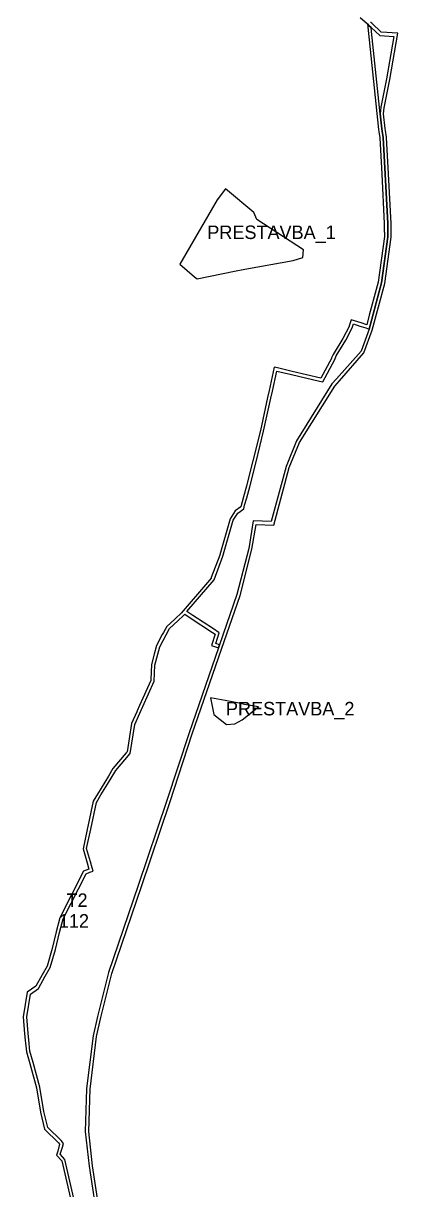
# Model space of a CAD drawing. Extents: x -477001 to -465642, y -1158278 to -1150672.
# Drawn here: x -475565 to -475233, y -1153120 to -1152085 of the extents above; entities that cross this region are included whole.
import ezdxf

# ---------------------------------------------------------------- set-up
doc = ezdxf.new("R2010")
doc.units = 0
for name, color, linetype in [('prestavba_n', 7, 'Continuous'), ('VPS_id', 7, 'Continuous'), ('VPS_n', 7, 'Continuous'), ('vyvlastneni_n', 7, 'Continuous')]:
    doc.layers.add(name, color=color, linetype=linetype)

msp = doc.modelspace()

# ---------------------------------------------------------------- linework, layer by layer
at = {"layer": 'prestavba_n'}
for p, q in [((-475385.7, -1152231.9), (-475392.9, -1152241.7)), ((-475360.4, -1152252.7), (-475385.7, -1152231.9)), ((-475392.9, -1152241.7), (-475426.2, -1152298.7)), ((-475357.7, -1152259.1), (-475360.4, -1152252.7)), ((-475316.3, -1152286.1), (-475357.7, -1152259.1)), ((-475316.8, -1152292.8), (-475316.3, -1152286.1)), ((-475368.3, -1152303.3), (-475325.4, -1152295.5)), ((-475325.4, -1152295.5), (-475316.8, -1152292.8)), ((-475426.2, -1152298.7), (-475413.1, -1152309.9)), ((-475413.1, -1152309.9), (-475410.8, -1152311.9)), ((-475385.9, -1152686.5), (-475398.9, -1152684.2)), ((-475373.6, -1152688.9), (-475385.9, -1152686.5)), ((-475384.8, -1152707.8), (-475377.4, -1152707.1))]:
    msp.add_line(p, q, dxfattribs=at)
for points in [[(-475410.8, -1152311.9), (-475377.7, -1152305.1), (-475368.3, -1152303.3)], [(-475398.9, -1152684.2), (-475396, -1152699), (-475384.8, -1152707.8)], [(-475377.4, -1152707.1), (-475370.7, -1152703.6), (-475356.4, -1152692.2), (-475368.8, -1152689.9), (-475373.6, -1152688.9)]]:
    msp.add_lwpolyline(points, dxfattribs=at)
at = {"layer": 'VPS_n'}
for p, q in [((-475265.9, -1152079.5), (-475259.5, -1152085.3)), ((-475259.5, -1152085.3), (-475257.8, -1152086.9)), ((-475257.8, -1152086.9), (-475259.5, -1152085.3)), ((-475259.5, -1152085.3), (-475249.7, -1152179)), ((-475257.8, -1152086.9), (-475256.2, -1152088.4)), ((-475256.2, -1152088.4), (-475257.8, -1152086.9)), ((-475255.8, -1152092.1), (-475256.2, -1152088.4)), ((-475248.1, -1152165.1), (-475255.8, -1152092.1)), ((-475243.7, -1152178.2), (-475245.1, -1152165.1)), ((-475249.7, -1152179), (-475249.4, -1152180.9)), ((-475249.4, -1152180.9), (-475248.4, -1152186.6)), ((-475246.7, -1152178.6), (-475246.7, -1152178.6)), ((-475246.7, -1152178.6), (-475246.7, -1152178.6)), ((-475238.4, -1152269.4), (-475238.5, -1152268.5)), ((-475273.9, -1152348.1), (-475275.7, -1152353.6)), ((-475271.1, -1152349), (-475273.9, -1152348.1)), ((-475265.1, -1152350.9), (-475271.1, -1152349)), ((-475257.9, -1152344.2), (-475260.1, -1152352.5)), ((-475273, -1152355.2), (-475272, -1152351.9)), ((-475272, -1152351.9), (-475266.3, -1152353.7)), ((-475266.3, -1152353.7), (-475265.2, -1152354)), ((-475265.2, -1152354), (-475260.9, -1152355.4)), ((-475260.1, -1152352.5), (-475265.1, -1152350.9)), ((-475288.6, -1152383.3), (-475287.3, -1152380.2)), ((-475339.4, -1152390.9), (-475342.4, -1152390.2)), ((-475326.3, -1152394), (-475339.4, -1152390.9)), ((-475291.5, -1152382.5), (-475300.8, -1152400)), ((-475299.2, -1152403.4), (-475288.6, -1152383.3)), ((-475340.1, -1152393.8), (-475327, -1152396.9)), ((-475327, -1152396.9), (-475302.2, -1152402.7)), ((-475300.8, -1152400), (-475326.3, -1152394)), ((-475302.2, -1152402.7), (-475299.2, -1152403.4)), ((-475351.7, -1152447.1), (-475345.4, -1152417.8)), ((-475358.5, -1152474.3), (-475351.7, -1152447.1)), ((-475364, -1152496.7), (-475358.5, -1152474.3)), ((-475364.8, -1152487.4), (-475366.9, -1152495.9)), ((-475366.9, -1152495.9), (-475369.6, -1152505.5)), ((-475366.7, -1152506.3), (-475364, -1152496.7)), ((-475369.4, -1152516.1), (-475368.6, -1152513)), ((-475368.6, -1152513), (-475366.7, -1152506.3)), ((-475378.8, -1152526.2), (-475374.8, -1152520)), ((-475374.8, -1152520), (-475369.4, -1152516.1)), ((-475387.9, -1152558.2), (-475378.8, -1152526.2)), ((-475395.8, -1152579.3), (-475387.9, -1152558.2)), ((-475419.9, -1152607.5), (-475395.8, -1152579.3)), ((-475414.6, -1152611), (-475419.9, -1152607.5)), ((-475430.7, -1152614.1), (-475437.9, -1152620.7)), ((-475435.5, -1152622.5), (-475428, -1152615.7)), ((-475421.8, -1152609.8), (-475416.9, -1152613)), ((-475416.9, -1152613), (-475397.3, -1152625.9)), ((-475396.3, -1152622.9), (-475414.6, -1152611)), ((-475444.1, -1152638.7), (-475435.5, -1152622.5)), ((-475440.8, -1152626), (-475441.8, -1152627.9)), ((-475437.9, -1152620.7), (-475440.8, -1152626)), ((-475448.5, -1152655.1), (-475444.1, -1152638.7)), ((-475449, -1152669.3), (-475448.5, -1152655.1)), ((-475452, -1152668.7), (-475462, -1152691)), ((-475459, -1152691.7), (-475449, -1152669.3)), ((-475451.9, -1152667.8), (-475452, -1152668.7)), ((-475462, -1152691), (-475464.1, -1152695.6)), ((-475464.5, -1152696.5), (-475469.1, -1152706.9)), ((-475466.3, -1152707.8), (-475461.7, -1152697.7)), ((-475464.1, -1152695.6), (-475464.5, -1152696.5)), ((-475461.7, -1152697.7), (-475459, -1152691.7)), ((-475470.3, -1152733.5), (-475466.3, -1152707.8)), ((-475473.1, -1152732.2), (-475473.8, -1152733)), ((-475489.7, -1152753.7), (-475499.3, -1152769.6)), ((-475496.3, -1152770.3), (-475490.4, -1152760.7)), ((-475507, -1152836.2), (-475511.7, -1152838)), ((-475508.5, -1152830.8), (-475507, -1152836.2)), ((-475504.2, -1152835.2), (-475505.7, -1152829.7)), ((-475503.3, -1152838), (-475504.2, -1152835.2)), ((-475530, -1152880.6), (-475509.5, -1152840.4)), ((-475509.5, -1152840.4), (-475506.1, -1152839.1)), ((-475506.1, -1152839.1), (-475503.3, -1152838)), ((-475533, -1152892.6), (-475530, -1152880.6)), ((-475536.8, -1152907.6), (-475533, -1152892.6)), ((-475541.5, -1152923.7), (-475536.8, -1152907.6)), ((-475545.8, -1152931.5), (-475541.5, -1152923.7)), ((-475533, -1153080.7), (-475534.7, -1153087)), ((-475532.4, -1153089.7), (-475530.6, -1153083.5)), ((-475530.6, -1153083.5), (-475529.6, -1153080)), ((-475534.7, -1153087), (-475535.7, -1153090.5)), ((-475535.7, -1153090.5), (-475531.1, -1153095.6)), ((-475528.3, -1153094.2), (-475532.4, -1153089.7))]:
    msp.add_line(p, q, dxfattribs=at)
for points in [[(-475245.1, -1152165.1), (-475244.5, -1152159.7), (-475239.6, -1152134.5), (-475232.6, -1152093.5), (-475247.3, -1152092.5), (-475255.7, -1152084.7), (-475256.5, -1152084.1), (-475256.7, -1152083.9)], [(-475256.2, -1152088.4), (-475248.6, -1152095.4), (-475236.1, -1152096.3), (-475242.5, -1152134), (-475247.5, -1152159.3), (-475248.1, -1152165.1)], [(-475248.1, -1152165.1), (-475246.7, -1152178.6), (-475246.7, -1152178.6)], [(-475246.7, -1152178.6), (-475246.7, -1152178.6), (-475248.1, -1152165.1)], [(-475246.7, -1152178.6), (-475246.4, -1152180.5), (-475245.4, -1152186.3), (-475245.4, -1152186.3)], [(-475245.4, -1152186.3), (-475245.4, -1152186.3), (-475246.4, -1152180.5), (-475246.7, -1152178.6)], [(-475242.4, -1152186.2), (-475242.5, -1152185.9), (-475243.4, -1152180), (-475243.7, -1152178.2)], [(-475260.9, -1152355.4), (-475258, -1152356.4), (-475247, -1152315.2), (-475241.3, -1152274.3), (-475241.3, -1152270.5), (-475241.5, -1152269.4), (-475241.5, -1152262.6), (-475243.7, -1152218.8), (-475245.4, -1152186.3)], [(-475245.4, -1152186.3), (-475243.7, -1152218.8), (-475241.5, -1152262.6), (-475241.5, -1152269.4), (-475241.3, -1152270.5), (-475241.3, -1152274.3), (-475247, -1152315.2), (-475258, -1152356.4)], [(-475248.4, -1152186.6), (-475246.7, -1152218.9), (-475244.5, -1152262.7)], [(-475238.5, -1152268.5), (-475238.5, -1152262.5), (-475240.7, -1152218.6), (-475242.4, -1152186.2)], [(-475244.5, -1152262.7), (-475244.5, -1152269.6), (-475244.3, -1152270.7), (-475244.3, -1152274.1)], [(-475244.3, -1152274.1), (-475249.9, -1152314.6), (-475257.9, -1152344.2)], [(-475255.2, -1152357.3), (-475244, -1152315.8), (-475238.3, -1152274.6), (-475238.3, -1152270.3), (-475238.4, -1152269.4)], [(-475275.7, -1152353.6), (-475275.8, -1152354), (-475281.4, -1152364.9), (-475290, -1152378.9), (-475290, -1152378.9)], [(-475287.3, -1152380.2), (-475278.8, -1152366.4), (-475273, -1152355.2)], [(-475258, -1152356.4), (-475265.2, -1152375.9), (-475287, -1152400.7)], [(-475284.4, -1152402.3), (-475262.6, -1152377.4), (-475255.2, -1152357.3)], [(-475290, -1152378.9), (-475291.3, -1152382.1), (-475291.5, -1152382.5)], [(-475342.4, -1152390.2), (-475346.9, -1152410.9), (-475348.3, -1152417.1), (-475348.3, -1152417.2)], [(-475345.4, -1152417.8), (-475343.9, -1152411.5), (-475340.1, -1152393.8)], [(-475287, -1152400.7), (-475291, -1152405.2), (-475322.6, -1152455.8), (-475331.7, -1152478.4), (-475345, -1152527.5)], [(-475342.7, -1152530.6), (-475328.9, -1152479.4), (-475319.9, -1152457.2), (-475288.5, -1152407), (-475284.4, -1152402.3)], [(-475348.3, -1152417.2), (-475354.6, -1152446.5), (-475354.6, -1152446.5)], [(-475354.6, -1152446.5), (-475361.4, -1152473.6), (-475364.8, -1152487.4)], [(-475372, -1152514.3), (-475377, -1152517.9), (-475381.5, -1152525), (-475390.7, -1152557.1)], [(-475369.6, -1152505.5), (-475369.6, -1152505.5), (-475372, -1152514.3)], [(-475345, -1152527.5), (-475361, -1152526.9), (-475365, -1152551.5), (-475375.5, -1152592.4)], [(-475372.6, -1152593.3), (-475362.1, -1152552.1), (-475358.5, -1152530), (-475342.7, -1152530.6)], [(-475390.7, -1152557.1), (-475390.7, -1152557.2), (-475398.3, -1152577.3)], [(-475398.3, -1152577.3), (-475398.5, -1152577.8), (-475401.7, -1152581.5)], [(-475401.7, -1152581.5), (-475425.1, -1152608.9), (-475430.1, -1152613.5), (-475430.7, -1152614.1)], [(-475375.5, -1152592.4), (-475390.9, -1152636.9), (-475391.9, -1152639.8), (-475391.9, -1152639.8), (-475417.9, -1152715.2), (-475438, -1152776.2), (-475463.1, -1152850.7), (-475489.6, -1152928.1), (-475499.3, -1152967.3), (-475503.1, -1152984.4), (-475509, -1153031.1)], [(-475506, -1153031.7), (-475500.2, -1152984.9), (-475496.4, -1152968), (-475486.7, -1152928.9), (-475460.3, -1152851.7), (-475435.1, -1152777.1), (-475415.1, -1152716.2), (-475389.1, -1152640.8), (-475372.6, -1152593.3)], [(-475428, -1152615.7), (-475422.9, -1152611), (-475421.8, -1152609.8)], [(-475441.8, -1152627.9), (-475446.9, -1152637.6), (-475449, -1152645.3)], [(-475397.3, -1152625.9), (-475394.7, -1152627.6), (-475398, -1152637.6), (-475391.9, -1152639.8), (-475390.9, -1152636.9), (-475394.2, -1152635.7), (-475391.2, -1152626.3), (-475396.3, -1152622.9)], [(-475449, -1152645.3), (-475451.5, -1152654.6), (-475451.9, -1152667.8)], [(-475469.1, -1152706.9), (-475469.2, -1152707), (-475473.1, -1152732.2)], [(-475473.8, -1152733), (-475485.6, -1152746.9), (-475489.7, -1152753.7)], [(-475490.4, -1152760.7), (-475483.1, -1152748.6), (-475470.3, -1152733.5)], [(-475499.3, -1152769.6), (-475503.2, -1152775.9), (-475508.6, -1152801.1)], [(-475505.4, -1152800.9), (-475500.3, -1152777), (-475496.3, -1152770.3)], [(-475508.6, -1152801.1), (-475512.2, -1152818.2), (-475508.5, -1152830.8)], [(-475505.7, -1152829.7), (-475509.1, -1152818.1), (-475505.4, -1152800.9)], [(-475511.7, -1152838), (-475532.9, -1152879.6), (-475536, -1152891.9), (-475539.7, -1152906.9), (-475544.2, -1152922.5), (-475548.4, -1152930.1), (-475554.2, -1152940.4), (-475561.8, -1152945.6), (-475565.3, -1152967.5), (-475564.1, -1152982.6), (-475563.5, -1152988.4), (-475562.4, -1152998.7), (-475559.5, -1153009.1)], [(-475529.6, -1153080), (-475531.8, -1153077.5), (-475543.6, -1153066), (-475547.1, -1153051.6), (-475550.5, -1153030), (-475556.6, -1153008.2), (-475559.4, -1152998.2), (-475560.5, -1152988.1), (-475561.1, -1152982.4), (-475562.3, -1152967.6), (-475559, -1152947.3), (-475551.9, -1152942.4), (-475545.8, -1152931.5)], [(-475559.5, -1153009.1), (-475553.5, -1153030.7), (-475550.1, -1153052.2), (-475546.4, -1153067.5), (-475534, -1153079.5), (-475533, -1153080.7)], [(-475509, -1153031.1), (-475509, -1153031.6), (-475510.2, -1153069.5), (-475506.9, -1153100.2), (-475498.7, -1153153)], [(-475495.8, -1153152.4), (-475503.9, -1153099.8), (-475507.2, -1153069.4), (-475506, -1153031.8), (-475506, -1153031.7)], [(-475511.1, -1153235.2), (-475512.5, -1153231.1), (-475517.9, -1153214.8), (-475521.2, -1153204.9), (-475525.3, -1153189.2), (-475525.6, -1153187.1), (-475516.8, -1153144.3), (-475528.3, -1153094.2)], [(-475531.1, -1153095.6), (-475519.9, -1153144.4), (-475528.7, -1153187), (-475528.3, -1153189.8), (-475524.1, -1153205.8), (-475520.8, -1153215.7), (-475515.3, -1153232), (-475513.9, -1153236.2), (-475508.5, -1153250.6), (-475505.8, -1153256.7), (-475500.9, -1153265.2), (-475496.9, -1153271.7), (-475486.2, -1153282.2), (-475476.4, -1153289.8), (-475468.6, -1153294.7), (-475459, -1153315.2), (-475453.4, -1153327.2), (-475445.8, -1153344.1), (-475428.9, -1153403.2)]]:
    msp.add_lwpolyline(points, dxfattribs=at)
at = {"layer": 'vyvlastneni_n'}
for p, q in [((-475265.9, -1152079.5), (-475259.5, -1152085.3)), ((-475259.5, -1152085.3), (-475257.8, -1152086.9)), ((-475257.8, -1152086.9), (-475259.5, -1152085.3)), ((-475259.5, -1152085.3), (-475249.7, -1152179)), ((-475257.8, -1152086.9), (-475256.2, -1152088.4)), ((-475256.2, -1152088.4), (-475257.8, -1152086.9)), ((-475255.8, -1152092.1), (-475256.2, -1152088.4)), ((-475248.1, -1152165.1), (-475255.8, -1152092.1)), ((-475243.7, -1152178.2), (-475245.1, -1152165.1)), ((-475249.7, -1152179), (-475249.4, -1152180.9)), ((-475249.4, -1152180.9), (-475248.4, -1152186.6)), ((-475246.7, -1152178.6), (-475246.7, -1152178.6)), ((-475246.7, -1152178.6), (-475246.7, -1152178.6)), ((-475238.4, -1152269.4), (-475238.5, -1152268.5)), ((-475273.9, -1152348.1), (-475275.7, -1152353.6)), ((-475271.1, -1152349), (-475273.9, -1152348.1)), ((-475265.1, -1152350.9), (-475271.1, -1152349)), ((-475257.9, -1152344.2), (-475260.1, -1152352.5)), ((-475273, -1152355.2), (-475272, -1152351.9)), ((-475272, -1152351.9), (-475266.3, -1152353.7)), ((-475266.3, -1152353.7), (-475265.2, -1152354)), ((-475265.2, -1152354), (-475260.9, -1152355.4)), ((-475260.1, -1152352.5), (-475265.1, -1152350.9)), ((-475288.6, -1152383.3), (-475287.3, -1152380.2)), ((-475339.4, -1152390.9), (-475342.4, -1152390.2)), ((-475326.3, -1152394), (-475339.4, -1152390.9)), ((-475291.5, -1152382.5), (-475300.8, -1152400)), ((-475299.2, -1152403.4), (-475288.6, -1152383.3)), ((-475340.1, -1152393.8), (-475327, -1152396.9)), ((-475327, -1152396.9), (-475302.2, -1152402.7)), ((-475300.8, -1152400), (-475326.3, -1152394)), ((-475302.2, -1152402.7), (-475299.2, -1152403.4)), ((-475351.7, -1152447.1), (-475345.4, -1152417.8)), ((-475358.5, -1152474.3), (-475351.7, -1152447.1)), ((-475364, -1152496.7), (-475358.5, -1152474.3)), ((-475364.8, -1152487.4), (-475366.9, -1152495.9)), ((-475366.9, -1152495.9), (-475369.6, -1152505.5)), ((-475366.7, -1152506.3), (-475364, -1152496.7)), ((-475369.4, -1152516.1), (-475368.6, -1152513)), ((-475368.6, -1152513), (-475366.7, -1152506.3)), ((-475378.8, -1152526.2), (-475374.8, -1152520)), ((-475374.8, -1152520), (-475369.4, -1152516.1)), ((-475387.9, -1152558.2), (-475378.8, -1152526.2)), ((-475395.8, -1152579.3), (-475387.9, -1152558.2)), ((-475419.9, -1152607.5), (-475395.8, -1152579.3)), ((-475414.6, -1152611), (-475419.9, -1152607.5)), ((-475430.7, -1152614.1), (-475437.9, -1152620.7)), ((-475435.5, -1152622.5), (-475428, -1152615.7)), ((-475421.8, -1152609.8), (-475416.9, -1152613)), ((-475416.9, -1152613), (-475397.3, -1152625.9)), ((-475396.3, -1152622.9), (-475414.6, -1152611)), ((-475444.1, -1152638.7), (-475435.5, -1152622.5)), ((-475440.8, -1152626), (-475441.8, -1152627.9)), ((-475437.9, -1152620.7), (-475440.8, -1152626)), ((-475448.5, -1152655.1), (-475444.1, -1152638.7)), ((-475449, -1152669.3), (-475448.5, -1152655.1)), ((-475452, -1152668.7), (-475462, -1152691)), ((-475459, -1152691.7), (-475449, -1152669.3)), ((-475451.9, -1152667.8), (-475452, -1152668.7)), ((-475462, -1152691), (-475464.1, -1152695.6)), ((-475464.5, -1152696.5), (-475469.1, -1152706.9)), ((-475466.3, -1152707.8), (-475461.7, -1152697.7)), ((-475464.1, -1152695.6), (-475464.5, -1152696.5)), ((-475461.7, -1152697.7), (-475459, -1152691.7)), ((-475470.3, -1152733.5), (-475466.3, -1152707.8)), ((-475473.1, -1152732.2), (-475473.8, -1152733)), ((-475489.7, -1152753.7), (-475499.3, -1152769.6)), ((-475496.3, -1152770.3), (-475490.4, -1152760.7)), ((-475507, -1152836.2), (-475511.7, -1152838)), ((-475508.5, -1152830.8), (-475507, -1152836.2)), ((-475504.2, -1152835.2), (-475505.7, -1152829.7)), ((-475503.3, -1152838), (-475504.2, -1152835.2)), ((-475530, -1152880.6), (-475509.5, -1152840.4)), ((-475509.5, -1152840.4), (-475506.1, -1152839.1)), ((-475506.1, -1152839.1), (-475503.3, -1152838)), ((-475533, -1152892.6), (-475530, -1152880.6)), ((-475536.8, -1152907.6), (-475533, -1152892.6)), ((-475541.5, -1152923.7), (-475536.8, -1152907.6)), ((-475545.8, -1152931.5), (-475541.5, -1152923.7)), ((-475533, -1153080.7), (-475534.7, -1153087)), ((-475532.4, -1153089.7), (-475530.6, -1153083.5)), ((-475530.6, -1153083.5), (-475529.6, -1153080)), ((-475534.7, -1153087), (-475535.7, -1153090.5)), ((-475535.7, -1153090.5), (-475531.1, -1153095.6)), ((-475528.3, -1153094.2), (-475532.4, -1153089.7))]:
    msp.add_line(p, q, dxfattribs=at)
for points in [[(-475245.1, -1152165.1), (-475244.5, -1152159.7), (-475239.6, -1152134.5), (-475232.6, -1152093.5), (-475247.3, -1152092.5), (-475255.7, -1152084.7), (-475256.5, -1152084.1), (-475256.7, -1152083.9)], [(-475256.2, -1152088.4), (-475248.6, -1152095.4), (-475236.1, -1152096.3), (-475242.5, -1152134), (-475247.5, -1152159.3), (-475248.1, -1152165.1)], [(-475248.1, -1152165.1), (-475246.7, -1152178.6), (-475246.7, -1152178.6)], [(-475246.7, -1152178.6), (-475246.7, -1152178.6), (-475248.1, -1152165.1)], [(-475246.7, -1152178.6), (-475246.4, -1152180.5), (-475245.4, -1152186.3), (-475245.4, -1152186.3)], [(-475245.4, -1152186.3), (-475245.4, -1152186.3), (-475246.4, -1152180.5), (-475246.7, -1152178.6)], [(-475242.4, -1152186.2), (-475242.5, -1152185.9), (-475243.4, -1152180), (-475243.7, -1152178.2)], [(-475260.9, -1152355.4), (-475258, -1152356.4), (-475247, -1152315.2), (-475241.3, -1152274.3), (-475241.3, -1152270.5), (-475241.5, -1152269.4), (-475241.5, -1152262.6), (-475243.7, -1152218.8), (-475245.4, -1152186.3)], [(-475245.4, -1152186.3), (-475243.7, -1152218.8), (-475241.5, -1152262.6), (-475241.5, -1152269.4), (-475241.3, -1152270.5), (-475241.3, -1152274.3), (-475247, -1152315.2), (-475258, -1152356.4)], [(-475248.4, -1152186.6), (-475246.7, -1152218.9), (-475244.5, -1152262.7)], [(-475238.5, -1152268.5), (-475238.5, -1152262.5), (-475240.7, -1152218.6), (-475242.4, -1152186.2)], [(-475244.5, -1152262.7), (-475244.5, -1152269.6), (-475244.3, -1152270.7), (-475244.3, -1152274.1)], [(-475244.3, -1152274.1), (-475249.9, -1152314.6), (-475257.9, -1152344.2)], [(-475255.2, -1152357.3), (-475244, -1152315.8), (-475238.3, -1152274.6), (-475238.3, -1152270.3), (-475238.4, -1152269.4)], [(-475275.7, -1152353.6), (-475275.8, -1152354), (-475281.4, -1152364.9), (-475290, -1152378.9), (-475290, -1152378.9)], [(-475287.3, -1152380.2), (-475278.8, -1152366.4), (-475273, -1152355.2)], [(-475258, -1152356.4), (-475265.2, -1152375.9), (-475287, -1152400.7)], [(-475284.4, -1152402.3), (-475262.6, -1152377.4), (-475255.2, -1152357.3)], [(-475290, -1152378.9), (-475291.3, -1152382.1), (-475291.5, -1152382.5)], [(-475342.4, -1152390.2), (-475346.9, -1152410.9), (-475348.3, -1152417.1), (-475348.3, -1152417.2)], [(-475345.4, -1152417.8), (-475343.9, -1152411.5), (-475340.1, -1152393.8)], [(-475287, -1152400.7), (-475291, -1152405.2), (-475322.6, -1152455.8), (-475331.7, -1152478.4), (-475345, -1152527.5)], [(-475342.7, -1152530.6), (-475328.9, -1152479.4), (-475319.9, -1152457.2), (-475288.5, -1152407), (-475284.4, -1152402.3)], [(-475348.3, -1152417.2), (-475354.6, -1152446.5), (-475354.6, -1152446.5)], [(-475354.6, -1152446.5), (-475361.4, -1152473.6), (-475364.8, -1152487.4)], [(-475372, -1152514.3), (-475377, -1152517.9), (-475381.5, -1152525), (-475390.7, -1152557.1)], [(-475369.6, -1152505.5), (-475369.6, -1152505.5), (-475372, -1152514.3)], [(-475345, -1152527.5), (-475361, -1152526.9), (-475365, -1152551.5), (-475375.5, -1152592.4)], [(-475372.6, -1152593.3), (-475362.1, -1152552.1), (-475358.5, -1152530), (-475342.7, -1152530.6)], [(-475390.7, -1152557.1), (-475390.7, -1152557.2), (-475398.3, -1152577.3)], [(-475398.3, -1152577.3), (-475398.5, -1152577.8), (-475401.7, -1152581.5)], [(-475401.7, -1152581.5), (-475425.1, -1152608.9), (-475430.1, -1152613.5), (-475430.7, -1152614.1)], [(-475375.5, -1152592.4), (-475390.9, -1152636.9), (-475391.9, -1152639.8), (-475391.9, -1152639.8), (-475417.9, -1152715.2), (-475438, -1152776.2), (-475463.1, -1152850.7), (-475489.6, -1152928.1), (-475499.3, -1152967.3), (-475503.1, -1152984.4), (-475509, -1153031.1)], [(-475506, -1153031.7), (-475500.2, -1152984.9), (-475496.4, -1152968), (-475486.7, -1152928.9), (-475460.3, -1152851.7), (-475435.1, -1152777.1), (-475415.1, -1152716.2), (-475389.1, -1152640.8), (-475372.6, -1152593.3)], [(-475428, -1152615.7), (-475422.9, -1152611), (-475421.8, -1152609.8)], [(-475441.8, -1152627.9), (-475446.9, -1152637.6), (-475449, -1152645.3)], [(-475397.3, -1152625.9), (-475394.7, -1152627.6), (-475398, -1152637.6), (-475391.9, -1152639.8), (-475390.9, -1152636.9), (-475394.2, -1152635.7), (-475391.2, -1152626.3), (-475396.3, -1152622.9)], [(-475449, -1152645.3), (-475451.5, -1152654.6), (-475451.9, -1152667.8)], [(-475469.1, -1152706.9), (-475469.2, -1152707), (-475473.1, -1152732.2)], [(-475473.8, -1152733), (-475485.6, -1152746.9), (-475489.7, -1152753.7)], [(-475490.4, -1152760.7), (-475483.1, -1152748.6), (-475470.3, -1152733.5)], [(-475499.3, -1152769.6), (-475503.2, -1152775.9), (-475508.6, -1152801.1)], [(-475505.4, -1152800.9), (-475500.3, -1152777), (-475496.3, -1152770.3)], [(-475508.6, -1152801.1), (-475512.2, -1152818.2), (-475508.5, -1152830.8)], [(-475505.7, -1152829.7), (-475509.1, -1152818.1), (-475505.4, -1152800.9)], [(-475511.7, -1152838), (-475532.9, -1152879.6), (-475536, -1152891.9), (-475539.7, -1152906.9), (-475544.2, -1152922.5), (-475548.4, -1152930.1), (-475554.2, -1152940.4), (-475561.8, -1152945.6), (-475565.3, -1152967.5), (-475564.1, -1152982.6), (-475563.5, -1152988.4), (-475562.4, -1152998.7), (-475559.5, -1153009.1)], [(-475529.6, -1153080), (-475531.8, -1153077.5), (-475543.6, -1153066), (-475547.1, -1153051.6), (-475550.5, -1153030), (-475556.6, -1153008.2), (-475559.4, -1152998.2), (-475560.5, -1152988.1), (-475561.1, -1152982.4), (-475562.3, -1152967.6), (-475559, -1152947.3), (-475551.9, -1152942.4), (-475545.8, -1152931.5)], [(-475559.5, -1153009.1), (-475553.5, -1153030.7), (-475550.1, -1153052.2), (-475546.4, -1153067.5), (-475534, -1153079.5), (-475533, -1153080.7)], [(-475509, -1153031.1), (-475509, -1153031.6), (-475510.2, -1153069.5), (-475506.9, -1153100.2), (-475498.7, -1153153)], [(-475495.8, -1153152.4), (-475503.9, -1153099.8), (-475507.2, -1153069.4), (-475506, -1153031.8), (-475506, -1153031.7)], [(-475511.1, -1153235.2), (-475512.5, -1153231.1), (-475517.9, -1153214.8), (-475521.2, -1153204.9), (-475525.3, -1153189.2), (-475525.6, -1153187.1), (-475516.8, -1153144.3), (-475528.3, -1153094.2)], [(-475531.1, -1153095.6), (-475519.9, -1153144.4), (-475528.7, -1153187), (-475528.3, -1153189.8), (-475524.1, -1153205.8), (-475520.8, -1153215.7), (-475515.3, -1153232), (-475513.9, -1153236.2), (-475508.5, -1153250.6), (-475505.8, -1153256.7), (-475500.9, -1153265.2), (-475496.9, -1153271.7), (-475486.2, -1153282.2), (-475476.4, -1153289.8), (-475468.6, -1153294.7), (-475459, -1153315.2), (-475453.4, -1153327.2), (-475445.8, -1153344.1), (-475428.9, -1153403.2)]]:
    msp.add_lwpolyline(points, dxfattribs=at)

# ---------------------------------------------------------------- texts
at = {"layer": 'prestavba_n'}
for s, p in [('PRESTAVBA_1', (-475401.8, -1152276.4)), ('PRESTAVBA_2', (-475385.2, -1152699.7))]:
    msp.add_text(s, height=12, dxfattribs=at).set_placement(p)
at = {"layer": 'VPS_id'}
msp.add_text('112', height=12, dxfattribs=at).set_placement((-475533.7, -1152888.3))
at = {"layer": 'VPS_n'}
msp.add_text('T2', height=12, dxfattribs=at).set_placement((-475526.9, -1152869.9))

doc.saveas('drawing.dxf')
